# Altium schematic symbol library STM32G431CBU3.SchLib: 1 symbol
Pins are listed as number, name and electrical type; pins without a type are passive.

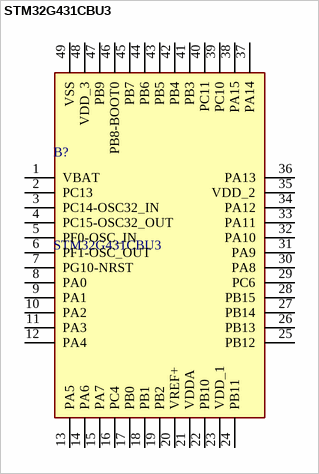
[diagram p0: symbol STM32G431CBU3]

## STM32G431CBU3
designator B?
MCU 32-bit ARM Cortex M4 RISC 128KB Flash 3.3V 48-Pin UFQFPN EP Tray; Manufacturer_Name: STMicroelectronics; Geometry.Height: 0.65mm
footprint QFN50P700X700X65-49N-D
pins: 1 VBAT, 2 PC13, 3 PC14-OSC32_IN, 4 PC15-OSC32_OUT, 5 PF0-OSC_IN, 6 PF1-OSC_OUT, 7 PG10-NRST, 8 PA0, 9 PA1, 10 PA2, 11 PA3, 12 PA4, 13 PA5, 14 PA6, 15 PA7, 16 PC4, 17 PB0, 18 PB1, 19 PB2, 20 VREF+, 21 VDDA, 22 PB10, 23 VDD_1, 24 PB11, 25 PB12, 26 PB13, 27 PB14, 28 PB15, 29 PC6, 30 PA8, 31 PA9, 32 PA10, 33 PA11, 34 PA12, 35 VDD_2, 36 PA13, 37 PA14, 38 PA15, 39 PC10, 40 PC11, 41 PB3, 42 PB4, 43 PB5, 44 PB6, 45 PB7, 46 PB8-BOOT0, 47 PB9, 48 VDD_3, 49 VSS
